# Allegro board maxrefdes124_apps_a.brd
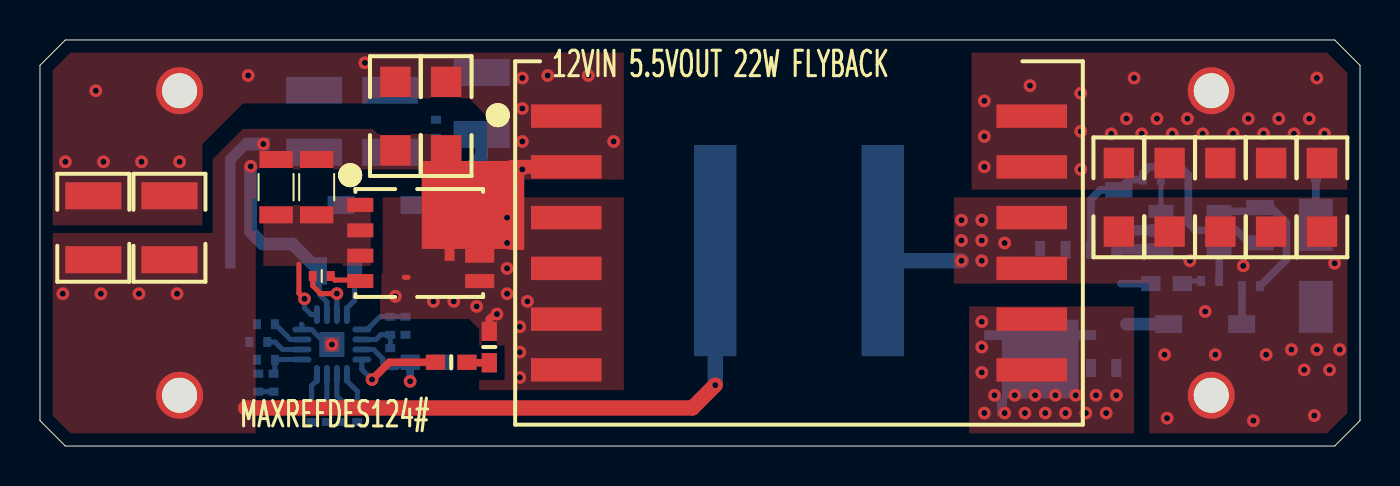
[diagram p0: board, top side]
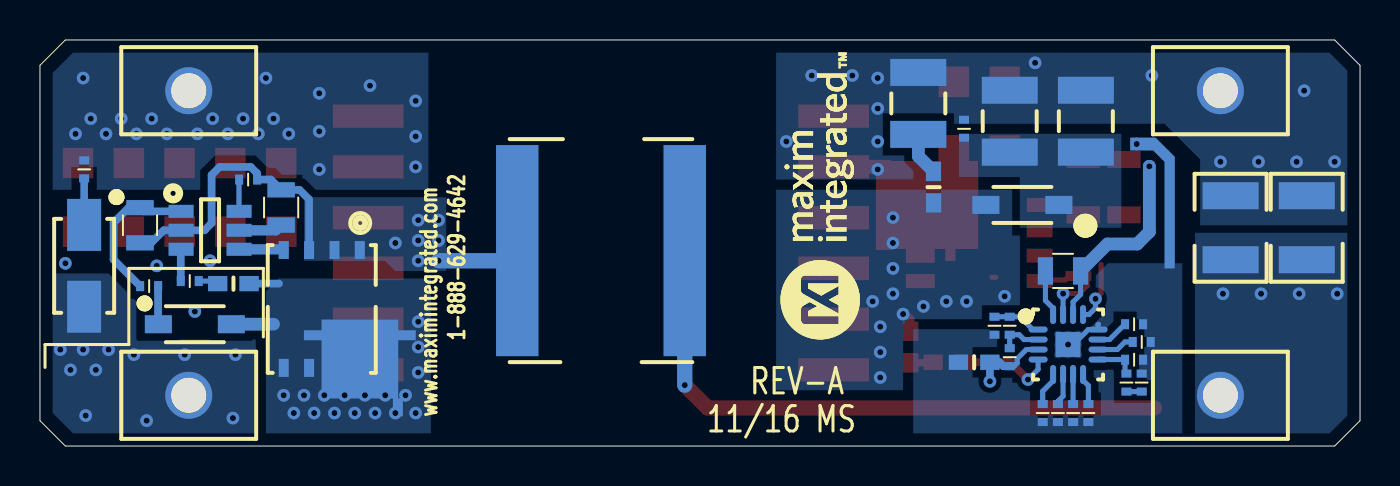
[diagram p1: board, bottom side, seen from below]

Outline 66.04 x 20.32 mm; copper layers: TOP, LAYER2, LAYER3, BOTTOM. Coordinates in mm from the lower left corner of the outline.
Outline path: 0,19.05 1.27,20.32 64.77,20.32 66.04,19.05 66.04,1.27 64.77,0 1.27,0 0,1.27 0,19.05

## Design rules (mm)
constraint set DEFAULT: min track width 0.254

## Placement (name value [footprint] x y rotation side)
C1  22UF  [1210]  2.67 10.92 90 top
C2  10UF  [1206]  17.78 16.51 90 top
C3  10UF  [1206]  20.32 16.51 90 top
C4  0.068UF  [0402]  19.81 15.88 90 bottom
C5  390PF  [0603]  21.34 12.95 90 bottom
C6  1UF  [0603]  19.3 4.19 180 bottom
C7  2.2UF  [0805]  14.86 8.76 0 bottom
C8  0.022UF  [0402]  10.92 5.21 180 bottom
C9  0.033UF  [0402]  10.92 3.17 270 bottom
C10  150PF  [0402]  11.3 4.32 0 bottom
C11  1000PF  [CAPC91102X254M]  37.97 9.78 0 bottom
C12  2.2UF  [0805]  61.04 11.05 90 bottom
C13  2.2UF  [0805]  53.98 11.94 270 bottom
C14  150UF  [1206]  53.98 12.45 90 top
C15  150UF  [1206]  56.52 12.45 90 top
C16  150UF  [1206]  59.05 12.45 90 top
C17  150UF  [1206]  61.59 12.45 90 top
C18  22UF  [1210]  6.48 10.92 90 top
C19  22UF  [1210]  6.48 10.92 90 bottom
C20  22UF  [1210]  2.67 10.92 90 bottom
C21  150UF  [1206]  64.14 12.45 90 top
D1  SMD110PL  [SOD3718X135M]  16.89 12.06 0 bottom
D2  1N4148W-7-F  [SOD3718X135M]  58.29 6.1 180 bottom
D3  6.2V  [DIO_SMA]  63.83 9.02 270 bottom
EV_KIT_BOX2  MEDIUM BOX  [EVKIT_PACKAGING]  32.96 -17.59 0 top
GNDO  FWJ-01-01-T-S  [SAMTEC_FWJ-01-01-X-X]  58.6 2.54 90 bottom
N1  BSC117N08NS5; RJK0651DPB-00#J5  [EK_PG-TDSON-8_LFPAK]  19.05 10.16 0 top
N2  BSC059N04LSG  [SON127P615X500X112-8M_POWERPAK_SINGLE]  51.94 6.86 270 bottom
NOREF  -  []  34.42 59.18 0 top
NOREF#2  -  []  0 19.05 0 top
NOREF#3  -  []  12.7 -8.26 0 top
NOREF#4  -  []  205.87 40.89 0 top
NOREF#5  -  []  65.33 0.56 0 top
NOREF#6  -  []  1.27 0 90 top
NOREF#7  -  []  6.99 17.78 0 top
NOREF#8  -  []  58.6 2.54 90 top
NOREF#9  -  []  26.92 7.37 90 bottom
PGND  FWJ-01-01-T-S  [SAMTEC_FWJ-01-01-X-X]  6.99 2.54 270 bottom
R1  7.5K  [RESC3225X65M]  17.53 16.26 270 bottom
R2  7.5K  [RESC3225X65M]  13.72 16.26 270 bottom
R3  470  [RESC3225X65M]  22.1 17.14 270 bottom
R4  0  [0402]  14.1 8.51 0 top
R5  10K  [0402]  18.29 6.02 90 bottom
R6  20K  [0402]  17.53 6.02 270 bottom
R7  150K  [0402]  17.53 4.45 270 bottom
R8  100K  [0603]  20.57 4.19 180 top
R9  5.6K  [0603]  22.48 4.95 270 top
R10  10K  [0402]  15.88 1.65 270 bottom
R11  OPEN  [0402]  15.11 1.65 270 bottom
R12  120K  [0402]  14.35 1.65 270 bottom
R13  51K  [0402]  13.59 1.65 270 bottom
R14  0.015  [1206#2]  13.84 12.95 90 top
R15  33K  [0402]  11.3 6.1 180 bottom
R16  2.2K  [0402]  11.68 3.17 270 bottom
R17  10  [0402]  60.58 8 180 bottom
R18  1.5K  [0402]  58.55 8.26 180 bottom
R19  68K  [0402]  55.63 13.34 180 bottom
R20  0  [0402]  63.83 13.84 270 bottom
R21  0.02  [1206#2]  11.81 12.95 90 top
R22  0  [0603]  56.36 8.13 180 bottom
T1  HR021698  [EK_XFMR_HR021698_750316327]  37.97 10.16 0 top
U1  MAX17690ATE+  [QFN50P300X300X80-17M]  14.61 5.08 180 bottom
U2  MAX17606AZT+  [SOT95P280X110-6M]  57.53 10.79 180 bottom
VIN  FWJ-01-01-T-S  [SAMTEC_FWJ-01-01-X-X]  6.99 17.78 90 bottom
VOUT  FWJ-01-01-T-S  [SAMTEC_FWJ-01-01-X-X]  58.6 17.78 90 bottom

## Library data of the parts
C1 C18-C20 = CAP_NP: alternate symbols: CAPC3225X270L; part number: CAP_NP_1210CAP-1210,22UF,20-0022U-G9
C2 C3 = CAP_NP: alternate symbols: CAPC3216X90L; part number: CAP_NP_1206CAP-1206,10UF,20-0010U-Y6
C4 = CAP_NP: alternate symbols: 0402_NOSILK,CAPC1005X50L; part number: CAP_NP_0402CAP-0402,0.068UF,20-0U068-04C
C5 = CAP_NP: alternate symbols: 0603_NOSILK,CAPC1608X90L; part number: CAP_NP_0603CAP-0603,390PF,20-0390P-CA14
C6 = CAP_NP: alternate symbols: (0603_NOSILK); part number: CAP_NP_0603CAP-0603,1UF,20-0001U-14
C7 C12 C13 = CAP_NP: alternate symbols: CAPC2012X145L,CAPC2012X140M; part number: CAP_NP_0805CAP-0805,2.2UF,20-002U2-04
C8 = CAP_NP: alternate symbols: 0402_NOSILK,CAPC1005X50L; part number: CAP_NP_0402CAP-0402,0.022UF,20-0U022-B60
C9 = CAP_NP: alternate symbols: 0402_NOSILK,CAPC1005X50L; part number: CAP_NP_0402CAP-0402,0.033UF,20-0U033-04C
C10 = CAP_NP: alternate symbols: 0402_NOSILK,CAPC1005X50L; part number: CAP_NP_0402CAP-0402,150PF,20-0150P-BA31
C11 = CAP_NP: alternate symbols: CAPC91102X254L; part number: CAP_NP_3640CAP-CAPC91102X254M,1000PF,20-1000P-CA85
C14-C17 C21 = CAP_NP: alternate symbols: CAPC3216X90L; part number: CAP_NP_1206CAP-1206,150UF,20-0150U-B57
D1 = DIO_SCHOTTKY: alternate symbols: SOD3718X135M_ALT; part number: DIO_SCHOTTKY_SOD3718X135M-SOD3718X135M,SMD110PL, 30-SMD110PL-00
D2 = DIO_SWITCH: part number: DIO_SWITCH_SOD-123-SOD3718X135M,1N4148W-7-F,30-1N4148W7F-00
D3 = DIO_ZENER: part number: DIO_ZENER_SMA-DIO_SMA,6.2V,30-SMAZ6V2-00
EV_KIT_BOX2 = EV_KIT_BOX: part number: EV_KIT_BOX_ACCESSORY-N/A,MEDIUM BOX,EVKIT_PACKAGING
GNDO PGND VIN VOUT = HEADER_1P: part number: HEADER_1P_TH-SAMTEC_FWJ-01-01-X-X,FWJ-01-01-T-S,01-FWJ0101TS1P-19
N1 = EK_TRAN_NCH_8P: part number: EK_TRAN_NCH_8P_COMBI_PG-TDSON-8_LFPAK-EK_PG-TDSON-8_LFPAK,BSC117N08NS5; RJK0651DPB-00#J5,90-BSC117N08NS5-23
N2 = TRAN_NCH_8P: part number: TRAN_NCH_8P_PG-TDSON-8-SON127P615X500X112-8M_POWERPAK_SINGLE,BSC059N04LSG,90-BSC059N04LSG-23
R1 R2 = RES: alternate symbols: RESC3225X70L; part number: RES_1210RES-RESC3225X65M,7.5K,80-007K5-BA51
R3 = RES: alternate symbols: RESC3225X70L; part number: RES_1210RES-RESC3225X65M,470,80-0470R-T8
R4 = RES: alternate symbols: (0402_NOSILK,RESC1005X50L); part number: RES_0402RES-0402,0,80-0000R-26B
R5 R10 = RES: alternate symbols: 0402_NOSILK,RESC1005X50L,RES0402-NOT_FOR_TEST; part number: RES_0402RES-0402,10K,80-0010K-23
R6 = RES: alternate symbols: (0402_NOSILK,RESC1005X50L); part number: RES_0402RES-0402,20K,80-0020K-23
R7 = RES: alternate symbols: (0402_NOSILK,RESC1005X50L); part number: RES_0402RES-0402,150K,80-0150K-23
R8 = RES: alternate symbols: 0603_NOSILK,RESC1608X90L; part number: RES_0603RES-0603,100K,80-0100K-24
R9 = RES: alternate symbols: 0603_NOSILK,RESC1608X90L; part number: RES_0603RES-0603,5.6K,80-005K6-24
R11 = EVK_GENERIC_RESISTORS: alternate symbols: 0402_NOSILK,RESC1005X50L; part number: EVK_GENERIC_RESISTORS_0402RES-0402,N/A
R12 = RES: alternate symbols: (0402_NOSILK,RESC1005X50L); part number: RES_0402RES-0402,120K,80-0120K-23
R13 = RES: alternate symbols: 0402_NOSILK,RESC1005X50L; part number: RES_0402RES-0402,51K,80-0051K-AA23
R14 = RES: alternate symbols: RESC3116X60L; part number: RES_1206RES-1206,0.015,80-0R015-BA25
R15 = RES: alternate symbols: (0402_NOSILK,RESC1005X50L); part number: RES_0402RES-0402,33K,80-0033K-23
R16 = RES: alternate symbols: (0402_NOSILK,RESC1005X50L); part number: RES_0402RES-0402,2.2K,80-002K2-23
R17 = RES: alternate symbols: (0402_NOSILK,RESC1005X50L); part number: RES_0402RES-0402,10,80-0010R-49
R18 = RES: alternate symbols: 0402_NOSILK,RESC1005X50L; part number: RES_0402RES-0402,1.5K,80-001K5-23
R19 = RES: alternate symbols: (0402_NOSILK,RESC1005X50L); part number: RES_0402RES-0402,68K,80-0068K-23
R20 = RES: alternate symbols: 0402_NOSILK,RESC1005X50L; part number: RES_0402RES-0402,0,80-0000R-BA38
R21 = RES: alternate symbols: RESC3116X60L; part number: RES_1206RES-1206,0.02,80-00R02-BA25
R22 = RES: alternate symbols: 0603_NOSILK,RESC1608X90L; part number: RES_0603RES-0603,0,80-0000R-27
T1 = EK_HR021698: part number: EK_HR021698_SMD_ALLPINS-EK_XFMR_HR021698_750316327,HR021698,N/A
U1 = MAX17690: part number: MAX17690_TQFN16-EP-QFN50P300X300X80-17M,MAX17690ATE+,10-MAX17690ATE-T
U2 = MAX17606: part number: MAX17606_SOT23-6-SOT95P280X110-6M,MAX17606AZT+,10-MAX17606AZT-Z

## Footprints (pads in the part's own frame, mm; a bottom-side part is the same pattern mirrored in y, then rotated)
0402
  rect 0.4x0.5 smd: 1(-0.45,0) 2(0.45,0)
0603
  rect 0.965x0.762 smd: 1(-0.787,0) 2(0.787,0)
0805
  rect 0.76x1.37 smd: 1(-0.88,0) 2(0.88,0)
1206
  rect 1.524x1.524 smd: 1(-1.714,0) 2(1.714,0)
1206#2
  rect 0.85x1.67 smd: 1(-1.385,0) 2(1.385,0)
1210
  rect 1.35x2.8 smd: 1(-1.6,0) 2(1.6,0)
CAPC91102X254M
  rect 2.12x10.56 smd: 1(-4.19,0) 2(4.19,0)
DIO_SMA
  rect 2.6x1.7 smd: A(2.05,0) C(-2.05,0)
EK_PG-TDSON-8_LFPAK
  rect 1.3x0.7 smd: 1(-3.025,1.905) 2(-3.025,0.635) 3(-3.025,-0.635) 4(-3.025,-1.905)
  rect 1.45x0.7 smd: 5(2.95,-1.905) 6(2.95,-0.635) 7(2.95,0.635)
  custom 1.4x1.4 smd: 8(2.95,1.905)
EK_XFMR_HR021698_750316327
  rect 3.535x1.17 smd: 1(-11.642,6.35) 2(-11.642,3.81) 3(-11.642,1.27) 4(-11.642,-1.27) 5(-11.642,-3.81) 6(-11.642,-6.35) 7(11.642,-6.35) 8(11.642,-3.81) 9(11.642,-1.27) 10(11.642,1.27) 11(11.642,3.81) 12(11.642,6.35)
QFN50P300X300X80-17M
  oval 0.95x0.3 smd: 1(-1.5,0.75) 2(-1.5,0.25) 3(-1.5,-0.25) 4(-1.5,-0.75) 9(1.5,-0.75) 10(1.5,-0.25) 11(1.5,0.25) 12(1.5,0.75)
  oval 0.3x0.95 smd: 5(-0.75,-1.5) 6(-0.25,-1.5) 7(0.25,-1.5) 8(0.75,-1.5) 13(0.75,1.5) 14(0.25,1.5) 15(-0.25,1.5) 16(-0.75,1.5)
  rect 1.25x1.25 smd: 17(0,0)
RESC3225X65M
  rect 1.35x2.8 smd: 1(-1.55,0) 2(1.55,0)
SAMTEC_FWJ-01-01-X-X
  round 2.35 hole 1.75: 1(0,0)
SOD3718X135M
  rect 1.35x0.9 smd: A(1.825,0) C(-1.825,0)
SON127P615X500X112-8M_POWERPAK_SINGLE
  rect 0.9x0.5 smd: 1(-2.95,1.905) 2(-2.95,0.635) 3(-2.95,-0.635) 4(-2.95,-1.905) 5(2.95,-1.905) 6(2.95,-0.635) 7(2.95,0.635)
  custom 1.209x1.209 smd: 8(2.95,1.905)
SOT95P280X110-6M
  rect 1.25x0.65 smd: 1(-1.45,0.95) 2(-1.45,0) 3(-1.45,-0.95) 4(1.45,-0.95) 5(1.45,0) 6(1.45,0.95)

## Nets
GNDO: C11.2 C12.1 C13.1 C14.1 C15.1 C16.1 C17.1 C21.1 D3.A GNDO.1 N2.1 N2.2 N2.3(S3) R19.2 T1.9 T1.10(NC_4) U2.2
PGND: C1.1 C2.1 C3.1 C7.1 C11.1 C18.1 C19.1 C20.1 PGND.1 R14.2 R21.2 U1.14
SGND: C6.1 C8.2 C9.1 C10.1 R5.1 R10.2 R11.2 R12.2 R13.2 R15.2 U1.12 U1.17
VIN: C1.2 C2.2 C3.2 C4.2 C6.2 C18.2 C19.2 C20.2 R1.1 R2.1 R3.1 R7.2 T1.1 T1.2 U1.3(VIN) VIN.1
DRN: R18.1 U2.3
GATE: N2.4 U2.4
LX: C5.1 D1.A N1.5 N1.6 N1.7 N1.8 R9.1 T1.3 T1.4 T1.5 T1.6
UNNAMED_1_CAPNP_I27_2: C9.2 R16.2
UNNAMED_1_CAPNP_I29_2: C10.2 R16.1 U1.9
UNNAMED_1_CAPNP_I44_1: C8.1 U1.10
UNNAMED_1_CAPNP_I52_1: C4.1 D1.C(K) R1.2 R2.2
UNNAMED_1_CAPNP_I56_2: C5.2 R3.2
UNNAMED_1_CAPNP_I67_2: C12.2 R17.1 U2.1(VIN)
UNNAMED_1_CAPNP_I74_2: C13.2 U2.5
UNNAMED_1_CAPNP_I91_2: C7.2 U1.16
UNNAMED_1_DIOSWITCH_I59_A: D2.A N2.5 N2.6 N2.7 N2.8 R22.2 T1.7 T1.8
UNNAMED_1_DIOSWITCH_I59_K: D2.C(K) R17.2
UNNAMED_1_DIOZENER_I83_K: D3.C(K) R20.2
UNNAMED_1_MAX17606_I82_TOFF: R19.1 U2.6
UNNAMED_1_MAX17690_I36_CS: N1.1 N1.2 N1.3(S3) R14.1 R21.1 U1.13
UNNAMED_1_MAX17690_I36_EN: R6.2 R7.1 U1.2
UNNAMED_1_MAX17690_I36_FB: R8.2 U1.4
UNNAMED_1_MAX17690_I36_NDRV: R4.1 U1.15
UNNAMED_1_MAX17690_I36_OVI: R5.2 R6.1 U1.1
UNNAMED_1_MAX17690_I36_RIN: R13.1 U1.8
UNNAMED_1_MAX17690_I36_RT: R15.1 U1.11
UNNAMED_1_MAX17690_I36_SET: R10.1 U1.5
UNNAMED_1_MAX17690_I36_TC: R11.1 U1.6
UNNAMED_1_MAX17690_I36_VCM: R12.1 U1.7
UNNAMED_1_RESSMD_I33_2: R8.1 R9.2
UNNAMED_1_RESSMD_I51_2: N1.4 R4.2
UNNAMED_1_RESSMD_I119_1: R18.2 R22.1
VOUT: C14.2 C15.2 C16.2 C17.2 C21.2 R20.1 T1.11 T1.12 VOUT.1

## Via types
v1: diameter 0.635, hole 0.305, TOP to BOTTOM, 101 vias

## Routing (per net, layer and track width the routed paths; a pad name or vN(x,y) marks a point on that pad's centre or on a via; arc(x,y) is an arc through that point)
GNDO: length 19
  BOTTOM w0.381: N2.3 52.58,12.34 53.05,12.82 C13.1 54.49,13.34 R19.2 55.18,13.64 55.5,13.97 57.05,13.97 57.45,13.56 57.45,11.15 57.81,10.79 U2.2 59.85,10.79 60.47,10.17 C12.1
  BOTTOM w0.762: v1(46.1,9.27) 42.67,9.27 C11.2
  vias: v1(46.1,11.3) v1(46.1,10.29) v1(47.12,11.3) v1(47.12,10.29) v1(47.12,9.27) v1(48.26,10.16) v1(56.26,4.57) v1(56.39,1.4) v1(57.53,9.27) v1(58.29,6.73) v1(58.8,4.57) v1(60.2,9.02) v1(60.71,1.27) v1(61.34,4.57) v1(62.61,4.83) v1(63.25,3.81) v1(63.75,1.52) v1(63.88,4.83) v1(64.52,3.81) v1(64.77,9.14) v1(65.02,4.83)
PGND: length 40.6
  TOP w0.762: 10.29,1.91 32.64,1.91 v1(33.78,3.05)
  BOTTOM w0.254: C7.1 13.98,7.59 14.35,7.21 U1.14
  BOTTOM w0.635: C7.1 12.63,10.11 11.15,10.11 10.54,10.72 v1(10.54,14)
  BOTTOM w0.762: C11.1 v1(33.78,3.05)
  vias: v1(1.14,7.62) v1(3.05,7.62) v1(4.95,7.62) v1(6.86,7.62) v1(11.18,15.11)
SGND: length 2.1
  BOTTOM w0.254: v1(14.61,5.08) 14.34,5.08 13.59,5.83 U1.12 13.11,6.07 13.08,6.1
VIN: length 20.8
  LAYER3 w1.016: v1(16.26,19.18) 16.26,5.5 v1(18.52,3.24)
  BOTTOM w0.254: U1.3 16.69,4.83 17.15,4.37 17.15,4.15 17.31,3.99 R7.2
  BOTTOM w0.381: v1(18.52,3.24) C6.2 18.03,4.19 17.84,3.99 R7.2
  vias: v1(1.27,14.22) v1(2.79,17.78) v1(3.17,14.22) v1(5.08,14.22) v1(6.99,14.22) v1(10.41,18.54) v1(24.13,18.41) v1(24.13,16.89) v1(24.13,15.24) v1(24.13,13.84) v1(25.4,18.54) v1(27.43,18.54) v1(28.7,15.24)
DRN: length 1.6
  BOTTOM w0.381: U2.3 59,9.83 R18.1
GATE: length 2.2
  BOTTOM w0.508: U2.4 53.88,9.84 N2.4
LX: length 1.1
  TOP w0.254: 18.22,8.45 18.41,8.45
  TOP w0.381: 22.48,5.62 R9.1 22.48,6.35 22.61,6.48
  vias: v1(17.78,7.49) v1(19.68,7.24) v1(20.7,7.24) v1(21.84,6.99) v1(22.86,6.6) v1(23.37,11.43) v1(23.37,10.16) v1(23.37,8.89) v1(23.37,7.62) v1(24,5.97) v1(24,4.7) v1(24,3.43) v1(24.38,7.24)
UNNAMED_1_CAPNP_I27_2: length 0.8
  BOTTOM w0.254: R16.2 C9.2
UNNAMED_1_CAPNP_I29_2: length 2.1
  BOTTOM w0.254: U1.9 11.77,4.33 C10.2 11.75,3.69 R16.1
UNNAMED_1_CAPNP_I44_1: length 1.9
  BOTTOM w0.254: U1.10 12.14,4.83 11.76,5.21 C8.1
UNNAMED_1_CAPNP_I56_2: length 2.2
  BOTTOM w0.635: C5.2 22.1,14.5 R3.2
UNNAMED_1_CAPNP_I67_2: length 7.5
  BOTTOM w0.381: U2.1 60.85,11.75 C12.2 61.6,11.93 62.36,11.17 62.36,9.33 R17.1
UNNAMED_1_CAPNP_I74_2: length 2.2
  BOTTOM w0.508: U2.5 54.24,10.79 C13.2
UNNAMED_1_CAPNP_I91_2: length 2.3
  BOTTOM w0.254: U1.16 15.36,6.9 15.74,7.28 C7.2
UNNAMED_1_DIOSWITCH_I59_A: length 3.6
  BOTTOM w0.381: R22.2 54.08,8.13
  BOTTOM w0.635: D2.A 54.36,6.1
  vias: v1(47.12,6.22) v1(47.12,4.95) v1(47.12,3.68) v1(47.24,1.65) v1(47.75,2.54) v1(48.26,1.65) v1(48.77,2.54) v1(49.28,1.65) v1(49.78,2.54) v1(50.29,1.65) v1(50.8,2.54) v1(51.31,1.65) v1(51.82,2.54) v1(52.32,1.65) v1(52.83,2.54) v1(53.34,1.65) v1(53.85,2.54)
UNNAMED_1_DIOSWITCH_I59_K: length 1.9
  BOTTOM w0.381: D2.C 60.13,6.11 R17.2
UNNAMED_1_DIOZENER_I83_K: length 2.3
  BOTTOM w0.381: R20.2 D3.C
UNNAMED_1_MAX17606_I82_TOFF: length 1.6
  BOTTOM w0.254: R19.1 56.08,13.33 U2.6
UNNAMED_1_MAX17690_I36_CS: length 3.1
  TOP w0.254: 12.95,9.09 12.95,7.65 v1(13.23,7.37)
  BOTTOM w0.254: v1(13.23,7.37) 13.23,6.91 13.56,6.58 U1.13
UNNAMED_1_MAX17690_I36_EN: length 2.2
  BOTTOM w0.254: U1.2 16.81,5.33 17.05,5.57 R6.2 R7.1
UNNAMED_1_MAX17690_I36_FB: length 4.7
  TOP w0.381: R8.2 17.48,4.19 v1(16.61,3.33)
  BOTTOM w0.254: v1(16.61,3.33) 16.1,3.83 U1.4
UNNAMED_1_MAX17690_I36_NDRV: length 2.9
  TOP w0.254: v1(14.86,7.63) 14.04,7.63 13.65,8.02 R4.1
  BOTTOM w0.254: U1.15 v1(14.86,7.63)
UNNAMED_1_MAX17690_I36_OVI: length 2.4
  BOTTOM w0.254: R5.2 R6.1 17.01,6.47 16.37,5.83 U1.1
UNNAMED_1_MAX17690_I36_RIN: length 1.6
  BOTTOM w0.254: U1.8 13.85,3.29 13.59,3.02 R13.1
UNNAMED_1_MAX17690_I36_RT: length 1.7
  BOTTOM w0.254: U1.11 12.53,5.33 11.76,6.1 R15.1
UNNAMED_1_MAX17690_I36_SET: length 1.7
  BOTTOM w0.254: R10.1 15.88,2.74 15.36,3.26 U1.5
UNNAMED_1_MAX17690_I36_TC: length 1.6
  BOTTOM w0.254: R11.1 15.11,2.24 14.86,2.5 U1.6
UNNAMED_1_MAX17690_I36_VCM: length 1.5
  BOTTOM w0.254: R12.1 14.35,2.1 U1.7
UNNAMED_1_RESSMD_I33_2: length 1.1
  TOP w0.381: R8.1 21.39,4.17 R9.2
UNNAMED_1_RESSMD_I51_2: length 1.6
  TOP w0.254: R4.2 14.75,8.31 15.97,8.31 N1.4
UNNAMED_1_RESSMD_I119_1: length 1
  BOTTOM w0.254: R18.2 57.28,8.26 R22.1
VOUT:
  vias: v1(47.24,17.27) v1(47.24,15.49) v1(47.24,13.97) v1(49.53,18.03) v1(52.07,17.65) v1(52.07,15.75) v1(52.07,13.84) v1(53.59,15.62) v1(54.36,16.38) v1(54.74,18.41) v1(55.12,15.62) v1(55.88,16.38) v1(56.64,15.62) v1(57.4,16.38) v1(58.17,15.62) v1(59.69,15.62) v1(60.45,16.38) v1(61.21,15.62) v1(61.98,16.38) v1(62.74,15.62) v1(63.5,16.38) v1(63.88,18.41) v1(64.26,15.62)

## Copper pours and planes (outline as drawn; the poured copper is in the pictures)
GNDO on TOP: 55.5,0.64 55.5,8.13 45.72,8.13 45.72,12.45 47.24,12.45 51.82,12.45 65.41,12.45 65.41,1.65 64.39,0.64
GNDO on BOTTOM: 48.26,8.76 48.77,9.27 52.83,9.27 52.83,12.45 45.72,12.45 45.72,8.76
GNDO on BOTTOM: 61.21,5.33 61.21,7.24 62.61,8.64 65.41,8.64 65.41,1.65 64.39,0.64 62.1,0.64 55.24,0.64 55.24,5.33
GNDO on LAYER2: 55.5,0.64 55.5,8.76 54.99,8.76 45.92,8.76 45.72,8.89 45.72,11.68 51.44,11.68 52.2,12.45 65.41,12.45 65.41,1.65 64.39,0.64
GNDO on LAYER3: 55.5,0.64 55.5,8.76 45.72,8.76 45.72,12.45 65.41,12.45 65.41,1.65 64.39,0.64
PGND on TOP: 10.79,0.64 10.79,13.84 21.08,13.84 21.08,15.62 16.89,15.62 16.64,15.88 10.16,15.88 8.64,14.35 8.64,10.67 0.64,10.67 0.64,1.52 1.52,0.64
PGND on BOTTOM: 0.64,10.67 0.64,1.52 1.52,0.64 8.26,0.64 8.26,10.67
PGND on LAYER2, LAYER3: 0.64,9.53 8.26,9.53 8.26,0.64 1.52,0.64 0.64,1.52
SGND on BOTTOM (solid shape): 11.49,14.8 10.35,14.8 9.78,14.22 9.78,8.89 9.27,8.89 9.27,14.48 10.22,15.43 11.49,15.43
SGND on BOTTOM: 22.35,5.84 17.4,5.84 17.4,3.17 15.88,3.17 15.88,6.73 15.75,6.73 13.34,9.14 8.89,9.14 8.89,0.64 22.35,0.64
VIN on TOP: 0.64,11.05 0.64,18.8 1.52,19.68 29.21,19.68 29.21,13.34 22.35,13.34 22.35,16.51 21.46,17.4 16.51,17.4 16.26,17.14 10.16,17.14 8.13,15.11 8.13,11.05
VIN on BOTTOM: 8,11.05 0.64,11.05 0.64,18.8 1.52,19.68 29.21,19.68 29.21,13.34 22.35,13.34 22.35,16.13 9.78,16.13 8,14.35
VIN on LAYER2, LAYER3: 0.64,10.79 0.64,18.8 1.52,19.68 8.89,19.68 8.89,11.43 8.89,10.8 8.26,10.79
LX on TOP: 21.97,2.79 21.97,3.3 23.24,3.3 23.24,5.03 22.86,5.03 22.86,5.26 22.1,5.26 22.1,5.03 21.97,5.03 21.97,5.84 21.46,6.35 17.02,6.35 17.02,7.52 17.08,7.52 17.08,12.45 29.21,12.45 29.21,2.79
LX on BOTTOM, LAYER2, LAYER3: 17.02,12.83 29.21,12.83 29.21,2.79 22.86,2.79 22.86,6.1 22.61,6.35 17.02,6.35
UNNAMED_1_CAPNP_I52_1 on BOTTOM: 20.07,15.62 20.07,13.46 17.02,13.46 17.02,10.92 11.94,10.92 11.94,15.62
UNNAMED_1_DIOSWITCH_I59_A on TOP: 54.74,0.64 46.48,0.64 46.48,6.99 54.74,6.99
UNNAMED_1_DIOSWITCH_I59_A on BOTTOM: 54.74,7.75 54.74,0.64 46.48,0.64 46.48,8.38 54.1,8.38
UNNAMED_1_DIOSWITCH_I59_A on LAYER2, LAYER3: 54.74,8.38 54.74,0.64 46.48,0.64 46.48,8.38
UNNAMED_1_MAX17690_I36_CS on TOP: 16.76,12.45 14.86,12.45 14.48,12.06 11.18,12.06 11.18,9.02 16.76,9.02
VOUT on TOP, LAYER2, LAYER3: 65.41,18.67 64.39,19.68 46.61,19.68 46.61,12.83 65.41,12.83
VOUT on BOTTOM: 46.61,12.83 46.61,19.68 64.39,19.68 65.41,18.67 65.41,12.83

Small or netless copper shapes (teardrops, artwork), in the pictures only: 1 on TOP

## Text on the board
Ref Des/Silkscreen Bottom: 1-888-629-4642 | www.maximintegrated.com | REV-A | 11/16 MS
Ref Des/Silkscreen Top: MAXREFDES124# | 12VIN 5.5VOUT 22W FLYBACK
FAB_NOTES: NOTES: | FINISH: | TESTING: | MISCELLANEOUS: | TOOLING: | 16.  VENDOR LOGO & DATE CODE REQUIRED IN INK ON BOTTOM SIDE ONLY. DATE CODE FORMAT MUST BE YYWW ONLY | 17.  FINAL ELECTRICAL TEST TO BE PERFORMED USING PROVIDED IPC-D-356A NETLIST OR ODB++ FORMAT FILE. | 18.  A TIME DOMAIN REFLECTOMETER REPORT FOR EACH IMPEDANCE CONTROLLED LAYER AND A CERTIFICATE | 15.  CHECK ALL THAT APPLY | 14.  CHECK ALL THAT APPLY | 19. IF PRESENT, ALL BLIND/BURIED VIAS WITH AN ASPECT RATIO <1:1 TO BE PLATED SHUT WITH COPPER WHEN | 20.  FOR ALL DRILL INFORMATION REFER TO DRILL CHART. | 21.  FINISHED SURFACE CONTACTS AND FILLED VIAS TO BE FREE OF ANY PITS. SCRATCHES PROBE MARKS | 23.  PEMNUT | 13.  DRILL SIZES ARE FINISHED HOLE SIZES. ALL HOLES SHALL BE LOCATED WITHIN .005 DTP. | 22.  THIEVING: | 9.  ALL TRACES FILLETED OPTION TO ENHANCE RELIABILITY AT PAD JUNCTIONS | 10.  LAYER TO LAYER REGISTRATIONS SHALL BE WITHIN .003 INCHES. | MATERIAL: | 11.  FINISHED COPPER WEIGHT/THICKNESS: | 12.  CHECK ALL THAT APPLY | 8.  IF STATED IN THE LAMINATION DIAGRAM, THE DIELECTRIC THICKNESS OF ANY | 1.  DIMENSIONS ARE IN INCHES (EXCEPT WHERE NOTED). | 3.  THE PCB SHALL BE FABRICATED TO IPC-6012, TYPE X, CLASS 2. | 4.  BOARD MATERIAL & CONSTRUCTION SHALL MEET THE REQUIREMENTS OF UL796 | 5.  OVERALL BOARD THICKNESS REFER TO LAMINATION DIAGRAM. TOLERANCE APPLIES | 6.  BOW & TWIST NOT TO EXCEED 0.0075 IN. (0.75%) PER LINEAR INCH. | 7.  PHOTO ETCH CIRCUITRY PER ENCLOSED GERBER RS274X OR ODB++ FORMAT FILE. | 2.  BOARD MATERIAL: | ( )  FINISH CONDUCTOR SURFACES: IMMERSION GOLD, 2-5 MICRO INCHES OVER | (X)  REFER TO LAMINATION DIAGRAM FOR FINISHED COPPER WEIGHT/THICKNESS REQUIREMENTS. | ( )  OTHER ________________________ | (X)  FINISH CONDUCTOR SURFACES: IMMERSION GOLD, 3-8 MICRO INCHES OVER | ( )  FINGERS TO BE GOLD PLATED. | ( )  LEAD FREE AND RoHS COMPLIANT PLATING. | (X)  GREEN SOLDERMASK OVER BARE COPPER/BARE GOLD (BOTH SIDES) WITH LIQUID PHOTO IMAGEABLE INK (LPI) | ( )  GREEN TAIYO PSR-4000 | ( )  ELECTRODEPOSITED HARD GOLD PLATE, TYPE 1 (99.7% MIN GOLD), GRADE C | (X)  APPLY SILKSCREEN USING A NON-CONDUCTIVE, WHITE EPOXY | MINIMUM BARREL PLATING OF .001 IN. PLATED HOLES SHALL NOT BE ROUGH OR IRREGULAR | SO AS TO HINDER PROPER SOLDER WICKING. | USED AS VIA-IN PAD OR AS A STACKED VIA. BLIND/BURIED VIAS WITH AN ASPECT RATIO >1:1 TO BE FILLED | WITH NON-CONDUCTIVE EPOXY. UNLESS OTHERWISE SPECIFIED. | ( )  NON-CONDUCTIVE EPOXY. FILL AND CAP ALL 0.XXXX INCH DRILLED VIAS. | ( )  SILVER. FILL AND CAP ALL 0.XXXX INCH DRILLED VIAS. | (REQUIRED UNLESS OTHERWISE SPECIFIED IN QUOTE) | THE PCB SHALL HAVE A VERIFICATION STAMP. | OF COMPLIANCE SHALL BE PROVIDED BY VENDOR AT TIME OF SHIPMENT. | OR OTHER DEFORMITIES THAT COULD EFFECT THE APPERANCE AND PERFORMACE OF THE CONTACT | SURFACE. CONTACTS ARE TO BE AS FLAT AS POSSIBLE. NOT TO EXCEED +/- 0.001" OF FLATNESS. | ( )  SUPPLIER MAY ADD THIEVING TO COMPENSATE FOR LOW COPPER DENSITY AREAS ON THIS DESIGN. | WHERE SPACING PERMITS. | LEGEND TO LEGEND +/- 0.007 INCHES | (X)  SUPPLIER MAY NOT ADD THIEVING TO COMPENSATE FOR LOW COPPER DENSITY AREAS ON THIS DESIGN. | ( )  PEMNUTS TO BE INSTALLED BY SUPPLIER. | ( )  PEMNUTS NOT TO BE INSTALLED BY SUPPLIER. | (X)  NOT APPLICABLE | CONTROLLED IMPEDANCE LAYER IS FOR REFERENCE ONLY. FINAL ACCEPTANCE | SHALL BE DETERMINED BY THESE LAYERS HAVING A CHARACTERISTIC | IMPEDANCE OF +/-10% OHMS AS STATED IN THE LAMINATION DIAGRAM. THE | VENDOR CAN MAKE ADJUSTMENTS AS LONG AS THE STATED IMPEDANCE AND | OVERALL BOARD THICKNESS IS MAINTAINED. ANY ADJUSTMENT MADE TO TRACE | WIDTH OR SPACING MUST HAVE PRIOR WRITTEN APPROVAL FROM MAXIM. | ( )  FILLETED | (X)  NOT FILLETED | (X)  ISOLA 370HR OR EQUIVALENT | ( )  NELCO-4000-13 | ( )  MEGTRON 6 | ( )  ROGERS 4350B | ( )  ROGERS 4003C | ( )  ISOLA-FR408HR OR EQUIVALENT | WORKMANSHIP SHALL CONFORM TO IPC-A-600, CLASS 2, CURRENT REVISIONS. | WITH FLAMMABILITY RATING OF 94V-O. | AFTER ALL LAMINATION AND PLATING PROCESSES. IT IS TO BE MEASURED FROM | TOP PCB METAL TO BOTTOM PCB METAL UNLESS OTHERWISE SPECIFIED. | BOW & TWIST SHOULD BE MEASURED PER IPC-TM-650, METHOD 2.4.22. | DRILL LOCATION AND SIZE CONTROLLED BY EXCELLON CNC DRILL FILE. | UNLESS OTHERWISE SPECIFIED | THE STARTING COPPER WEIGHT/THICKNESS CAN VARY AS LONG AS THE FINISHED COPPER | WEIGHT/THICKNESS IS NOT LESS THAN THE SPECIFIED VALUE. UNLESS OTHERWISE SPECIFIED. | (KNOOP HARDNESS 130-200), CLASS 1 (50-100 MICRO INCHES THICK) IN ACCORDANCE WITH MIL-G-45204C. | GENERAL SURFACING REQUIREMENTS MUST MEET ANSI/IPC-A-600(CURRENT REV) SECTION 4.0, | CLASS 3 (50-100 MICROINCHES THICK) OVER ELECTRODEPOSITED NICKEL PLATE | IN ACCORDANCE WITH ANSI/IPC-A-600D, SECTION 4.0, CLASS 3 (200-600 MICROINCHES THICK). | 100 MICRO INCHES MINIMUM OF ELECTROLESS NICKEL. | 118-236 MICRO INCHES MINIMUM OF ELECTROLESS NICKEL. | PER ARTWORK. | BASED INK PER ARTWORK. | (USE CHECKED ITEMS FOR MATERIAL) | (USE CHECKED ITEMS FOR PLATING) | (USE CHECKED ITEMS FOR TOOLING) | UNLESS OTHERWISE SPECIFIED: | VINCENT LI | 11/09/2016 | 12VIN 5.5VOUT 22W FLYBACK CONVERTER | P2 | A | P1 | REVISION RELEASE | PRODUCTION RELEASE | INITIAL RELEASE | MAXREFDES124_APPS_A | VL | 08/31/16 | 11/03/16 | 07/05/16
DIMENSION: SLOT | x4 corners
User.16: FIGURE | SIZE | 12.0 | 68.898 | TOLERANCE | +3.0/-10.0 | +3.0/-3.0 | PLATED | ALL UNITS ARE IN MILS | QTY | 101 | 4 | NOTES | DRILL CHART: TOP to BOTTOM
User.22: 1"
